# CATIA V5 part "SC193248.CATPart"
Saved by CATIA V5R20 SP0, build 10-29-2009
Part number: SC193248
Revision: ANY
Definition: UNKNOWN
Nomenclature: SC193248
Source: Unknown
Bounding box of the stored display mesh (mm): x -9.696 to 9.217, y 0 to 32, z -48 to 0
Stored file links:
  C:\Users\Utente\Desktop\IO LAVORO\3D X SITO CF\CUMSA\3D files CG\CG 864857\SC193248.CATPart
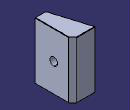
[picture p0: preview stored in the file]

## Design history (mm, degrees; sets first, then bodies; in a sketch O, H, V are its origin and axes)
Body1 "Chaflán2" (main body)
  Solid1: solid without history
